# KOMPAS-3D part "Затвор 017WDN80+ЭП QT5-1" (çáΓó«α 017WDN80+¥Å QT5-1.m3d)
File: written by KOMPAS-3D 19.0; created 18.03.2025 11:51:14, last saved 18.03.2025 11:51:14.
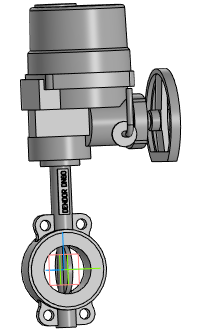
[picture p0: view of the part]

Document properties: Полное имя файла: Затвор 017WDN80+ЭП QT5-1.a3d

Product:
- Part/product: Затвор 017WDN80+ЭП QT5-1
    Масса: 44.9939

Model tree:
1. Операция без истории:1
